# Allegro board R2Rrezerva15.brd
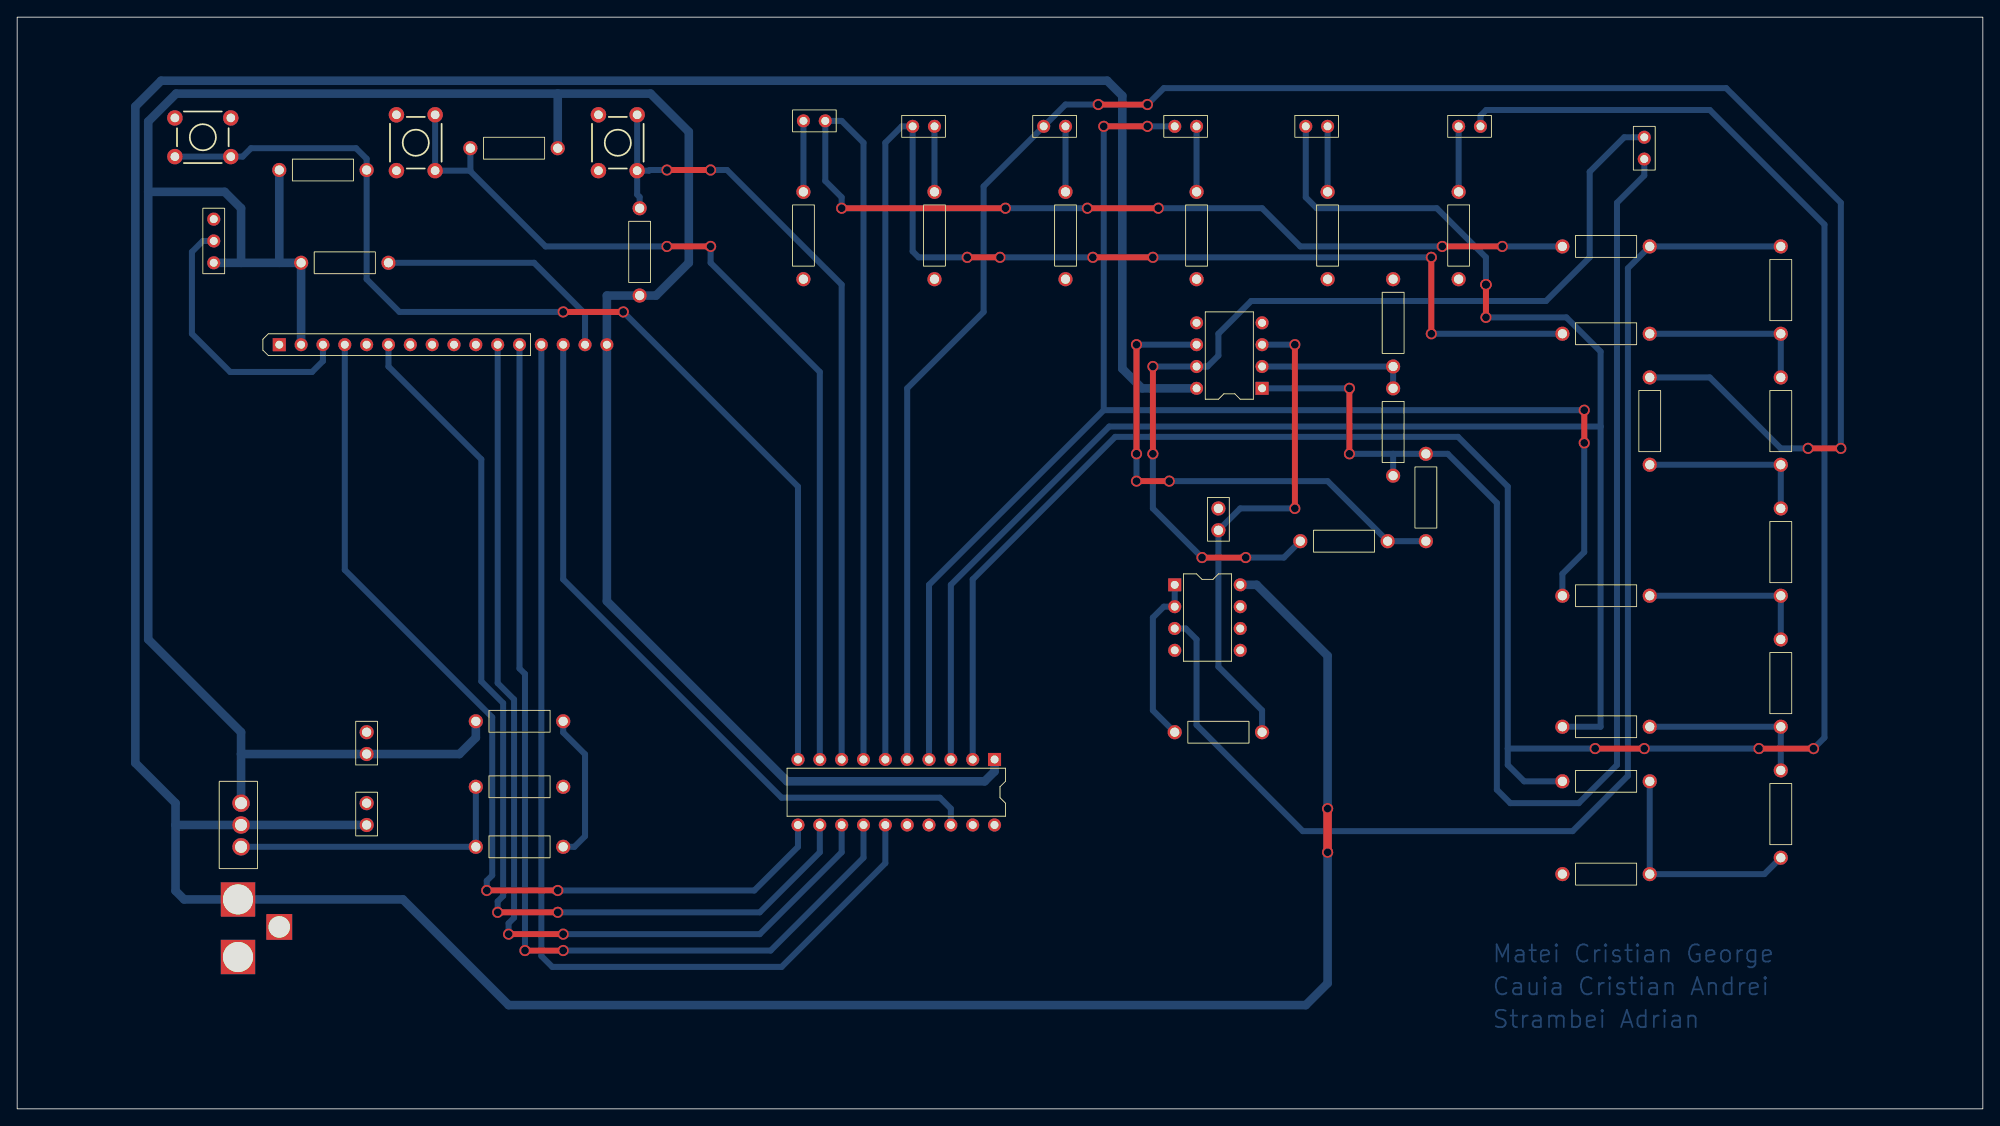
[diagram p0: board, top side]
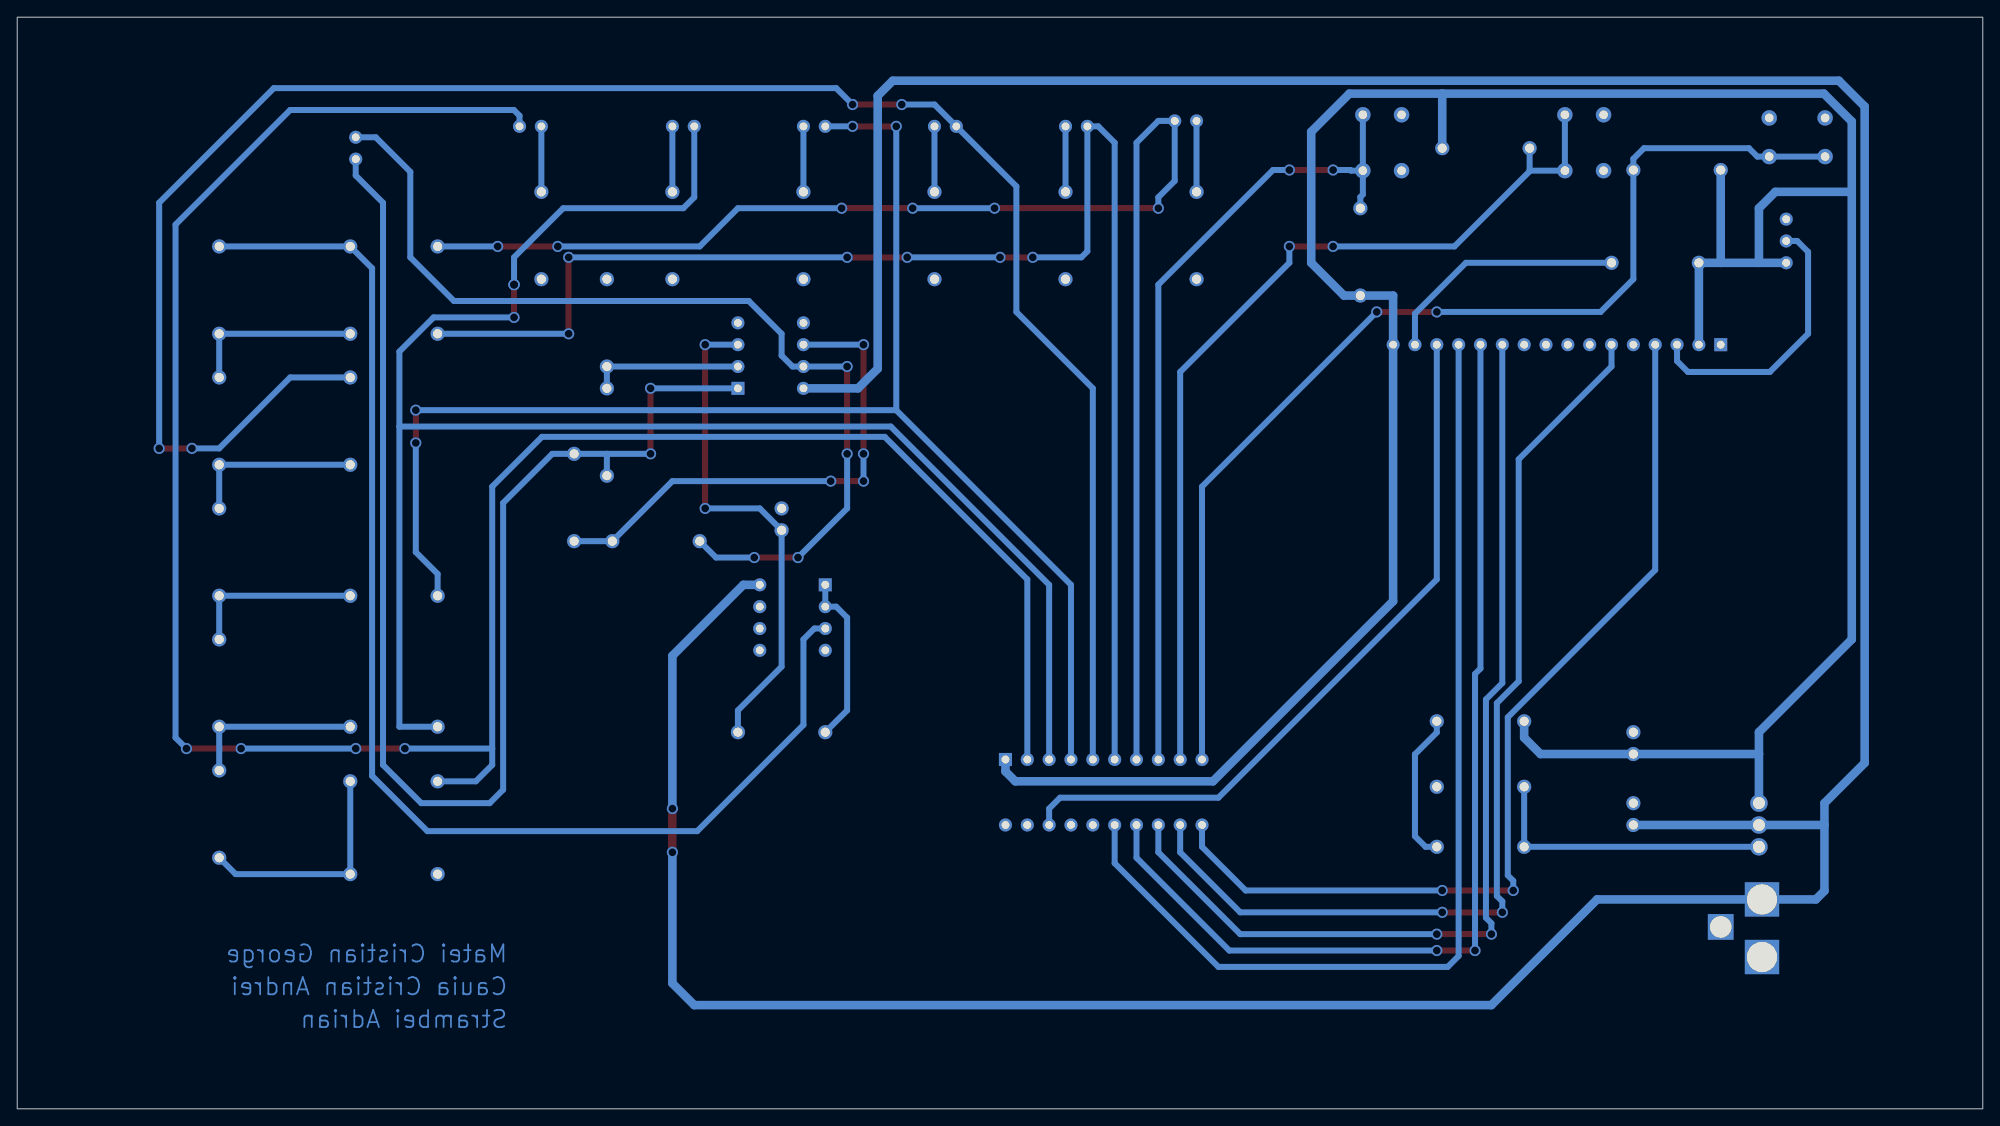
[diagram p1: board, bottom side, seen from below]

Outline 228.6 x 127 mm; copper layers: TOP, BOTTOM. Coordinates in mm from the lower left corner of the outline.
Outline path: rectangle 0,0 228.6,127

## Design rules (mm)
nets with their own width: min track width 0.7; nets N00328 N00336 N00340 N00355 N00395 N00470 N01662 N01669 N01683 N01690 N01717 N006340 N006500 N006660 N006820 N006980 N007140 N20855 N23488 N23661 N24189 N24193 N25824 N25853 N29134 N35057 N35516 N35592 N35638 N35656 N35674 N35692 N35721 N209781 SW1 SW2 SW3
nets with their own width: min track width 1; nets 0 9V VCC

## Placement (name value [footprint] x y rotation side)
C3  10nf  [CAPCK05]  139.7 67.31 0 top
C4  10u  [CAPCK05]  40.64 35.56 180 top
C5  10u  [CAPCK05]  40.64 43.81 180 top
D1  MLED81  [JUMPER2]  93.98 114.94 180 top
D2  MLED81  [JUMPER2]  104.14 114.3 0 top
D3  MLED81  [JUMPER2]  119.38 114.3 0 top
D4  MLED81  [JUMPER2]  134.62 114.3 0 top
D5  MLED81  [JUMPER2]  149.86 114.3 0 top
D6  MLED81  [JUMPER2]  170.18 114.3 180 top
J1  Speaker  [JUMPER2]  189.23 110.49 90 top
J2  LCD 1602  [SIP16]  30.48 88.9 90 top
J3  CON3  [JACK_DC2]  30.48 10.16 90 top
R2  1k  [RES400]  205.1 90.17 0 top
R3  1k  [RES400]  205.1 74.93 0 top
R4  1k  [RES400]  205.1 59.69 0 top
R5  1k  [RES400]  205.1 44.45 0 top
R6  1k  [RES400]  205.1 29.21 0 top
R7  2k  [RES400]  179.7 38.1 270 top
R8  2k  [RES400]  179.7 44.45 270 top
R9  2k  [RES400]  179.7 59.69 270 top
R10  2k  [RES400]  189.87 85.09 180 top
R11  2k  [RES400]  179.7 90.17 270 top
R12  2k  [RES400]  179.7 100.33 270 top
R13  2k  [RES400]  179.7 27.31 270 top
R14  470  [RES400]  167.64 96.52 0 top
R15  470  [RES400]  152.4 96.52 0 top
R16  470  [RES400]  137.16 96.52 0 top
R17  470  [RES400]  121.92 96.52 0 top
R18  470  [RES400]  106.68 96.52 0 top
R19  470  [RES400]  91.44 96.52 0 top
R20  10k  [RES400]  160.02 86.36 0 top
R22  10k  [RES400]  163.83 66.04 0 top
R23  1k  [RES400]  63.5 37.47 90 top
R24  470  [RES400]  63.5 45.09 90 top
R25  150  [RES400]  53.34 30.48 270 top
R26  33k  [RES400]  134.62 43.81 270 top
R27  10k  [RES400]  160.02 73.66 0 top
R28  10k  [RES400]  149.22 66.04 270 top
R29  1k  [JUMPER3]  22.86 103.5 270 top
R30  10k  [RES400]  40.64 109.22 90 top
R33  1k  [RES400]  33.02 98.43 270 top
R34  10k  [RES400]  52.7 111.76 270 top
R35  10k  [RES400]  72.39 104.78 180 top
SW7  SW_TC_SPST  [SW_SCHURTER_13019306L]  21.59 113.03 90 top
SW8  SW_TC_SPST  [SW_SCHURTER_13019306L]  46.35 112.4 180 top
SW9  SW_TC_SPST  [SW_SCHURTER_13019306L]  69.85 112.4 180 top
U1  MSP430G2553  [DIP20]  113.66 40.64 270 top
U7  LM317K  [TO220AB]  26.03 30.48 270 top
U9  LM358  [DIP8_3]  144.78 83.82 180 top
U10  LM358  [DIP8_3]  134.62 60.96 0 top

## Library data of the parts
C3 = C: Tolerance: ***; User Part Number: ***; signal model: DEFAULT_CAPACITOR_10000pF_1_2
C4 C5 = C: Tolerance: ***; User Part Number: ***; signal model: DEFAULT_CAPACITOR_1e+07pF_1_2
D1-D6 = MLED81: User Part Number: ***
J1 = CON2: User Part Number: ***
J2 = CON16: User Part Number: ***
J3 = CON3
R2-R6 R23 R33 = R: Tolerance: ***; User Part Number: ***; signal model: DEFAULT_RESISTOR_1000OHM_2_1
R7-R13 = R: Tolerance: ***; User Part Number: ***; signal model: DEFAULT_RESISTOR_2000OHM_2_1
R14-R19 R24 = R: Tolerance: ***; User Part Number: ***; signal model: DEFAULT_RESISTOR_470OHM_2_1
R20 R22 R27 R28 R30 R34 R35 = R: Tolerance: ***; User Part Number: ***; signal model: DEFAULT_RESISTOR_10000OHM_2_1
R25 = R: Tolerance: ***; User Part Number: ***; signal model: DEFAULT_RESISTOR_150OHM_2_1
R26 = R: Tolerance: ***; User Part Number: ***; signal model: DEFAULT_RESISTOR_33000OHM_2_1
R29 = POT: User Part Number: ***
SW7-SW9 = SW_TC_SPST
U1 = MSP430G2553_4: Tolerance: ***; User Part Number: ***
U7 = LM317T
U9 = LM358: Tolerance: ***; User Part Number: ***
U10 = LM358_0: Tolerance: ***; User Part Number: ***

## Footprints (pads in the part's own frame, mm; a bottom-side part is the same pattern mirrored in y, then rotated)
CAPCK05
  round 1.651 hole 1.067: 1(0,0) 2(0,2.54)
DIP8_3
  rect 1.524x1.524 hole 0.914: 1(0,0)
  round 1.524 hole 0.914: 2(0,-2.54) 3(0,-5.08) 4(0,-7.62) 5(7.62,-7.62) 6(7.62,-5.08) 7(7.62,-2.54) 8(7.62,0)
DIP20
  rect 1.524x1.524 hole 0.914: 1(0,0)
  round 1.524 hole 0.914: 2(0,-2.54) 3(0,-5.08) 4(0,-7.62) 5(0,-10.16) 6(0,-12.7) 7(0,-15.24) 8(0,-17.78) 9(0,-20.32) 10(0,-22.86) 11(7.62,-22.86) 12(7.62,-20.32) 13(7.62,-17.78) 14(7.62,-15.24) 15(7.62,-12.7) 16(7.62,-10.16) 17(7.62,-7.62) 18(7.62,-5.08) 19(7.62,-2.54) 20(7.62,0)
JACK_DC2
  rect 4x4 hole 3.5: 1(14.2,4.8) 2(7.5,4.8)
  rect 3x3 hole 2.5: 3(11,0)
JUMPER2
  round 1.524 hole 0.914: 1(0,0) 2(2.54,0)
JUMPER3
  round 1.524 hole 0.914: 1(0,0) 2(2.54,0) 3(5.08,0)
RES400
  round 1.651 hole 1.067: 1(0,0) 2(0,10.16)
SIP16
  rect 1.524x1.524 hole 0.914: 1(0,0)
  round 1.524 hole 0.914: 2(0,-2.54) 3(0,-5.08) 4(0,-7.62) 5(0,-10.16) 6(0,-12.7) 7(0,-15.24) 8(0,-17.78) 9(0,-20.32) 10(0,-22.86) 11(0,-25.4) 12(0,-27.94) 13(0,-30.48) 14(0,-33.02) 15(0,-35.56) 16(0,-38.1)
SW_SCHURTER_13019306L
  round 1.8 hole 1: 1(-2.25,-3.25) 2(-2.25,3.25) 3(2.25,3.25) 4(2.25,-3.25)
TO220AB
  round 2.032 hole 1.397: 1(0,0) 2(-2.54,0) 3(-5.08,0)

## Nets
9V: C4.2 J3.1 U7.2(IN) U9.8(V+) U10.8(V+)
VCC: C5.2 J2.2 J2.16 R24.2 R29.3(2) R30.2 R33.1 R34.2 R35.2 U1.1(DVCC) U7.3(OUT)
0: C3.2 C4.1 C5.1 J2.1 J2.5 J3.2 J3.3 R13.1 R14.1 R15.1 R16.1 R17.1 R18.1 R19.1 R20.2 R23.1 R29.1 SW7.3 SW8.3 SW9.3 U1.20(GROUND) U9.4(V-) U9.5(+) U10.4(V-)
SW1: R30.1 SW7.1 SW7.2 U1.10(P2_2)
SW2: R34.1 SW8.1 SW8.2 U1.9(P2_1)
SW3: R35.1 SW9.1 SW9.2 U1.8(P2_0/CS(B0))
N00328: R2.1 R3.2 R11.2
N00336: R4.1 R5.2 R9.2
N00340: R5.1 R6.2 R8.2
N00355: R2.2 R12.2 U10.3(+)
N00395: R3.1 R4.2 R10.2
N00470: R6.1 R7.2 R13.2
N01662: D5.1(A) R8.1 U1.3(P1_1/A1/RXD)
N01669: D4.1(A) R9.1 U1.4(P1_2/A2/TXD)
N01683: D2.1(A) R11.1 U1.6(P1_4/A4)
N01690: D1.1(A) R12.1 U1.7(P1_5/A5/SCK(B0))
N01717: D3.1(A) R10.1 U1.5(P1_3/A3/PUSH2)
N006340: D6.2(C) R14.2
N006500: D5.2(C) R15.2
N006660: D4.2(C) R16.2
N006820: D3.2(C) R17.2
N006980: D2.2(C) R18.2
N007140: D1.2(C) R19.2
N20855: R23.2 R25.1 U7.1(ADJ)
N23488: C3.1 R26.2 U9.3(+)
N23661: R26.1 U10.1(OUT) U10.2(-)
N24189: R20.1 R27.2 U9.2(-)
N24193: J1.1 R22.2 R27.1 U9.1(OUT)
N25824: R22.1 R28.2 U9.6(-)
N25853: J1.2 R28.1 U9.7(OUT)
N29134: D6.1(A) R7.1 U1.2(P1_0/A0/RED_LED)
N35057: J2.3 R29.2(T)
N35516: J2.4 U1.11(P2_3)
N35592: J2.6 U1.12(P2_4)
N35638: J2.11 U1.13(P2_5)
N35656: J2.12 U1.14(P1_6/A6/SCL/MISO(B0)/GREEN LED)
N35674: J2.13 U1.15(P1_7/A7/SDA/MOSE(B0))
N35692: J2.14 U1.18(P2_7/XOUT)
N35721: J2.15 R33.2
N209781: R24.1 R25.2

Pads without a net: J2 7 8 9 10; SW7 4; SW8 4; SW9 4; U1 16 17 19; U10 5 6 7

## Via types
v1: diameter 1.3, hole 0.9, TOP to BOTTOM, 57 vias

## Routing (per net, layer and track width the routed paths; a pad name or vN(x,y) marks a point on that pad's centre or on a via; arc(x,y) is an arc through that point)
9V: length 465.7
  TOP w1: v1(152.4,29.85) v1(152.4,34.93)
  BOTTOM w1: C4.2 U7.2 18.41,33.02 ; 18.41,33.02 18.41,35.56 13.74,40.24 13.74,116.61 16.74,119.61 126.77,119.61 128.52,117.86 128.52,86.11 130.81,83.82 U9.8 ; 18.41,33.02 18.41,25.36 19.41,24.36 J3.1 44.85,24.36 57.15,12.06 149.86,12.06 152.4,14.61 v1(152.4,29.85) ; U10.8 144.14,60.96 152.4,52.71 v1(152.4,34.93)
VCC: length 352.1
  BOTTOM w1: 15.24,106.68 24.13,106.68 26.03,104.78 26.03,98.43 ; 15.24,106.68 15.24,114.87 18.48,118.11 62.87,118.11 ; 15.24,106.68 15.24,54.61 26.03,43.81 26.03,41.28 ; J2.2 R33.1 30.48,98.43 ; 62.87,118.11 73.66,118.11 78.1,113.67 78.1,98.43 74.29,94.62 R35.2 68.58,94.62 J2.16 68.58,59.06 89.54,38.1 112.51,38.1 113.66,39.25 U1.1 ; 62.87,118.11 R34.2 ; 26.03,98.43 30.48,98.43 ; 26.03,98.43 R29.3 ; 26.03,41.28 51.44,41.28 53.34,43.18 R24.2 ; 26.03,41.28 U7.3 ; 30.48,98.43 R30.2
SW1: length 129.1
  TOP w0.7: v1(63.5,92.71) v1(70.49,92.71)
  BOTTOM w0.7: SW7.2 SW7.1 26.22,110.78 27.2,111.76 39.4,111.76 40.64,110.52 R30.1 40.64,96.52 44.45,92.71 v1(63.5,92.71) ; U1.10 90.81,72.39 v1(70.49,92.71)
SW2: length 109.8
  TOP w0.7: v1(75.56,100.33) v1(80.64,100.33)
  BOTTOM w0.7: v1(80.64,100.33) 80.64,98.43 93.34,85.73 U1.9 ; 52.63,109.15 SW8.2 SW8.1 ; 52.63,109.15 61.44,100.33 v1(75.56,100.33) ; 52.63,109.15 52.7,109.22 R34.1
SW3: length 95.6
  TOP w0.7: v1(75.56,109.22) v1(80.64,109.22)
  BOTTOM w0.7: U1.8 95.88,95.88 82.55,109.22 v1(80.64,109.22) ; SW9.1 SW9.2 ; SW9.2 73.48,109.15 73.55,109.22 v1(75.56,109.22) ; SW9.2 72.1,106.37 72.39,106.08 R35.1
N00328: length 20.3
  BOTTOM w0.7: R3.2 R2.1 R11.2
N00336: length 20.3
  BOTTOM w0.7: R9.2 R4.1 R5.2
N00340: length 20.3
  BOTTOM w0.7: R8.2 R5.1 R6.2
N00355: length 148.9
  BOTTOM w0.7: R2.2 R12.2 187.32,97.79 187.32,38.73 180.9,32.31 149.51,32.31 137.16,44.66 137.16,54.61 135.89,55.88 U10.3
N00395: length 20.3
  BOTTOM w0.7: R4.2 R3.1 R10.2
N00470: length 26.8
  BOTTOM w0.7: R7.2 R13.2 203.2,27.31 R6.1
N01662: length 205.7
  TOP w0.7: v1(170.81,95.88) v1(170.81,92.07)
  BOTTOM w0.7: v1(170.81,92.07) 180.17,92.07 184.15,88.09 184.15,79.38 ; v1(170.81,95.88) 170.81,99.06 165.1,104.78 151.13,104.78 149.86,106.05 D5.1 ; R8.1 184.15,44.45 184.15,79.38 ; 184.15,79.38 127,79.38 108.58,60.96 U1.3
N01669: length 168.9
  TOP w0.7: v1(131.44,114.3) v1(126.37,114.3) ; v1(182.25,81.28) v1(182.25,77.47)
  BOTTOM w0.7: 126.37,81.28 v1(182.25,81.28) ; 126.37,81.28 106.04,60.96 U1.4 ; 126.37,81.28 v1(126.37,114.3) ; R9.1 179.7,62.23 182.25,64.77 v1(182.25,77.47) ; D4.1 v1(131.44,114.3)
N01683: length 175
  TOP w0.7: v1(125.09,99.06) v1(132.08,99.06) ; v1(164.46,99.06) v1(164.46,90.17) ; v1(110.49,99.06) v1(114.3,99.06)
  BOTTOM w0.7: v1(164.46,90.17) R11.1 ; U1.6 100.96,112.4 102.87,114.3 D2.1 104.14,99.76 104.84,99.06 v1(110.49,99.06) ; v1(132.08,99.06) v1(164.46,99.06) ; v1(114.3,99.06) v1(125.09,99.06)
N01690: length 173.9
  TOP w0.7: v1(95.88,104.78) v1(114.94,104.78) ; v1(165.74,100.33) v1(172.72,100.33) ; v1(124.46,104.78) v1(132.71,104.78)
  BOTTOM w0.7: v1(114.94,104.78) v1(124.46,104.78) ; v1(132.71,104.78) 144.78,104.78 149.22,100.33 v1(165.74,100.33) ; v1(172.72,100.33) R12.1 ; v1(95.88,104.78) 95.88,106.05 93.98,107.95 D1.1 95.88,114.94 98.43,112.4 U1.7
N01717: length 234.5
  TOP w0.7: v1(212.09,76.84) v1(208.28,76.84) ; v1(131.44,116.84) v1(125.73,116.84)
  BOTTOM w0.7: v1(131.44,116.84) 133.35,118.75 198.75,118.75 212.09,105.41 v1(212.09,76.84) ; R10.1 196.85,85.09 205.1,76.84 v1(208.28,76.84) ; v1(125.73,116.84) 121.92,116.84 D3.1 112.39,107.31 112.39,92.71 103.5,83.82 U1.5
N006340: length 7.6
  BOTTOM w0.7: R14.2 D6.2
N006500: length 7.6
  BOTTOM w0.7: R15.2 D5.2
N006660: length 7.6
  BOTTOM w0.7: R16.2 D4.2
N006820: length 7.6
  BOTTOM w0.7: R17.2 D3.2
N006980: length 7.6
  BOTTOM w0.7: R18.2 D2.2
N007140: length 8.3
  BOTTOM w0.7: D1.2 R19.2
N20855: length 34.3
  BOTTOM w0.7: R23.2 R25.1 U7.1
N23488: length 58.4
  TOP w0.7: v1(148.59,88.9) v1(148.59,69.85)
  BOTTOM w0.7: R26.2 144.78,46.36 139.7,51.44 v1(139.7,67.31) 142.24,69.85 v1(148.59,69.85) ; U9.3 v1(148.59,88.9)
N23661: length 20
  BOTTOM w0.7: R26.1 132.08,46.36 132.08,57.15 133.35,58.42 U10.2 U10.1
N24189: length 17.8
  BOTTOM w0.7: R27.2 R20.1 U9.2
N24193: length 161.5
  TOP w0.7: v1(154.94,83.82) v1(154.94,76.2)
  BOTTOM w0.7: U9.1 v1(154.94,83.82) ; v1(154.94,76.2) 160.02,76.2 ; 160.02,76.2 R27.1 ; 160.02,76.2 R22.2 166.37,76.2 172.08,70.49 172.08,37.12 173.65,35.56 181.61,35.56 186.06,40 186.06,105.41 189.23,108.59 J1.1
N25824: length 59.4
  TOP w0.7: v1(130.18,88.9) v1(130.18,76.2) ; v1(130.18,73.03) v1(133.99,73.03)
  BOTTOM w0.7: U9.6 v1(130.18,88.9) ; v1(130.18,76.2) v1(130.18,73.03) ; R22.1 R28.2 152.4,73.03 v1(133.99,73.03)
N25853: length 112.3
  TOP w0.7: v1(132.08,86.36) v1(132.08,76.2) ; v1(137.79,64.13) v1(142.88,64.13)
  BOTTOM w0.7: v1(137.79,64.13) 132.08,69.85 v1(132.08,76.2) ; v1(142.88,64.13) 147.32,64.13 R28.1 ; v1(132.08,86.36) U9.7 138.43,86.36 139.7,87.63 139.7,90.17 143.51,93.98 177.8,93.98 182.88,99.06 182.88,109.01 186.9,113.03 J1.2
N29134: length 276.1
  TOP w0.7: v1(208.91,41.91) v1(202.56,41.91) ; v1(189.23,41.91) v1(183.51,41.91)
  BOTTOM w0.7: v1(202.56,41.91) v1(189.23,41.91) ; R7.1 175.26,38.1 173.35,40 173.35,41.91 ; U1.2 111.12,61.6 127.7,78.18 167.57,78.18 173.35,72.39 173.35,41.91 ; v1(208.91,41.91) 210.19,43.18 210.19,102.87 196.85,116.21 170.85,116.21 170.18,115.54 D6.1 ; 173.35,41.91 v1(183.51,41.91)
N35057: length 32.1
  BOTTOM w0.7: J2.3 35.56,87 34.29,85.73 24.76,85.73 20.32,90.17 20.32,99.69 21.59,100.97 R29.2
N35516: length 111.7
  TOP w0.7: v1(54.61,25.4) v1(62.87,25.4)
  BOTTOM w0.7: U1.11 90.81,30.48 85.72,25.4 v1(62.87,25.4) ; v1(54.61,25.4) 54.61,26.53 55.25,27.16 55.25,45.55 38.1,62.69 J2.4
N35592: length 115.4
  TOP w0.7: v1(55.88,22.86) v1(62.87,22.86)
  BOTTOM w0.7: v1(62.87,22.86) 86.36,22.86 93.34,29.85 U1.12 ; v1(55.88,22.86) 55.88,24.13 56.51,24.77 56.51,47.2 53.97,49.74 53.97,75.56 43.18,86.36 J2.6
N35638: length 115.5
  TOP w0.7: v1(57.15,20.32) v1(63.5,20.32)
  BOTTOM w0.7: v1(63.5,20.32) 86.36,20.32 95.88,29.85 U1.13 ; v1(57.15,20.32) 57.15,21.59 57.78,22.23 57.78,47.62 55.88,49.53 J2.11
N35656: length 118.4
  TOP w0.7: v1(63.5,18.42) v1(59.06,18.42)
  BOTTOM w0.7: v1(63.5,18.42) 87.63,18.42 98.43,29.21 U1.14 ; v1(59.06,18.42) 59.06,50.59 58.42,51.23 J2.12
N35674: length 121.1
  BOTTOM w0.7: U1.15 100.96,28.57 88.9,16.51 62.23,16.51 60.96,17.78 J2.13
N35692: length 85.3
  BOTTOM w0.7: U1.18 108.58,34.93 107.31,36.19 88.9,36.19 63.5,61.6 J2.14
N35721: length 28.9
  BOTTOM w0.7: R33.2 60.12,98.43 66.04,92.5 J2.15
N209781: length 17.5
  BOTTOM w0.7: R24.1 63.5,43.78 66.04,41.24 66.04,31.72 64.8,30.48 R25.2

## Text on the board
BOTTOM: Matei Cristian George | Cauia Cristian Andrei | Strambei Adrian
